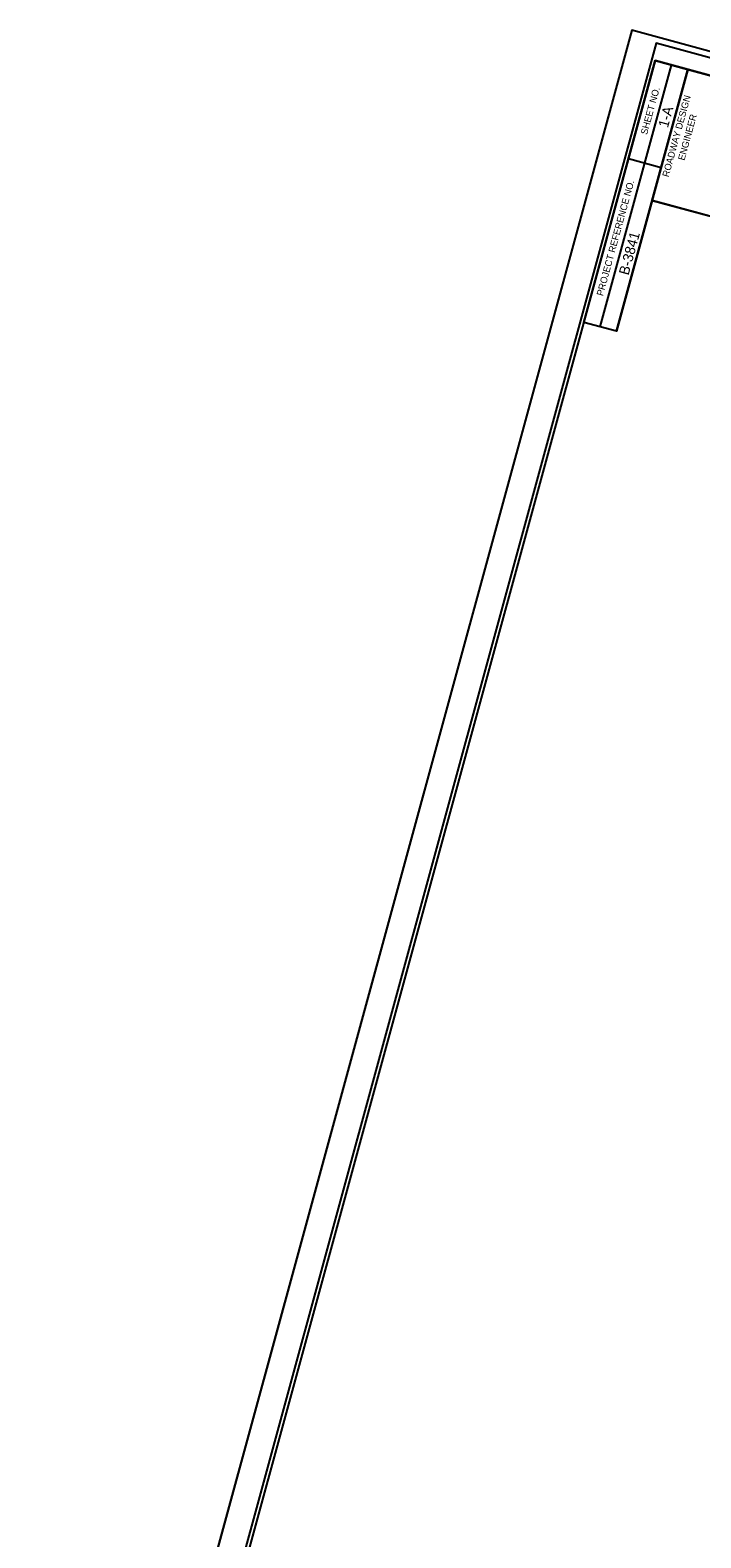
# Model space of a CAD drawing. Extents: x 2076126 to 2079903, y 925480 to 928006.
# Drawn here: x 2076126 to 2076620, y 926895 to 928006 of the extents above; entities that cross this region are included whole.
import ezdxf

# ---------------------------------------------------------------- set-up
doc = ezdxf.new("R2010")
doc.units = 0
for name, color, linetype in [('Sheet Cutting Line CELL', 7, 'Continuous'), ('Sheet Data Field CELL', 7, 'Continuous'), ('Sheet Plan CELL', 7, 'Continuous'), ('Sheet Plot Border Inside CELL', 7, 'Continuous'), ('Sheet Plot Border Outside CELL', 7, 'Continuous')]:
    doc.layers.add(name, color=color, linetype=linetype)

msp = doc.modelspace()

# ---------------------------------------------------------------- linework, layer by layer
at = {"layer": 'Sheet Cutting Line CELL'}
msp.add_line((2076568.9, 928005.9), (2076125.9, 926381.7), dxfattribs=at)
at = {"layer": 'Sheet Plan CELL'}
for p, q in [((2076545.6, 927787.2), (2076598.2, 927980.2)), ((2076557.7, 927784), (2076610.3, 927977)), ((2076557.7, 927784), (2076610.3, 927977)), ((2076566.4, 927911.2), (2076590.6, 927904.6)), ((2076584, 927880.5), (2076692.5, 927850.9))]:
    msp.add_line(p, q, dxfattribs=at)
for points in [[(2076586.1, 927983.6), (2076191.4, 926536.4), (2077204.4, 926260.1), (2077599.1, 927707.3)], [(2076533.5, 927790.6), (2076586.1, 927983.6), (2076610.3, 927977), (2076557.7, 927784)], [(2076584, 927880.5), (2076610.3, 927977), (2076718.8, 927947.4), (2076692.5, 927850.9)]]:
    msp.add_lwpolyline(points, close=True, dxfattribs=at)
at = {"layer": 'Sheet Plot Border Inside CELL'}
msp.add_lwpolyline([(2077166.4, 926111.4), (2077604.8, 927718.7), (2076587, 927996.3), (2076148.6, 926389)], close=True, dxfattribs=at)
at = {"layer": 'Sheet Plot Border Outside CELL'}
msp.add_lwpolyline([(2077182.3, 926093.6), (2077625.3, 927717.7), (2076568.9, 928005.9), (2076125.9, 926381.7)], close=True, dxfattribs=at)

# ---------------------------------------------------------------- texts
at = {"layer": 'Sheet Data Field CELL'}
for s, p in [('1-A', (2076595.5, 927933.5)), ('B-3841', (2076566.5, 927824.9))]:
    msp.add_text(s, height=7.5, rotation=74.7434, dxfattribs=at).set_placement(p)
at = {"layer": 'Sheet Plan CELL'}
for s, p in [('SHEET NO.', (2076580.2, 927928.5)), ('ROADWAY DESIGN', (2076596.1, 927897.3)), ('ENGINEER', (2076607.7, 927909.5)), ('PROJECT REFERENCE NO.', (2076547.7, 927809.7))]:
    msp.add_text(s, height=5, rotation=74.7434, dxfattribs=at).set_placement(p)

doc.saveas('drawing.dxf')
